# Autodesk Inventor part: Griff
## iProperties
Created: 2005-12
Part Number: Griff
Document SubType Name: Modeling
Designer: Benno
Manufacturer: Standard
Standards Organization: Custom
Material: PVC hart
Author: Benno
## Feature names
1. Drehung1 [Revolution]
